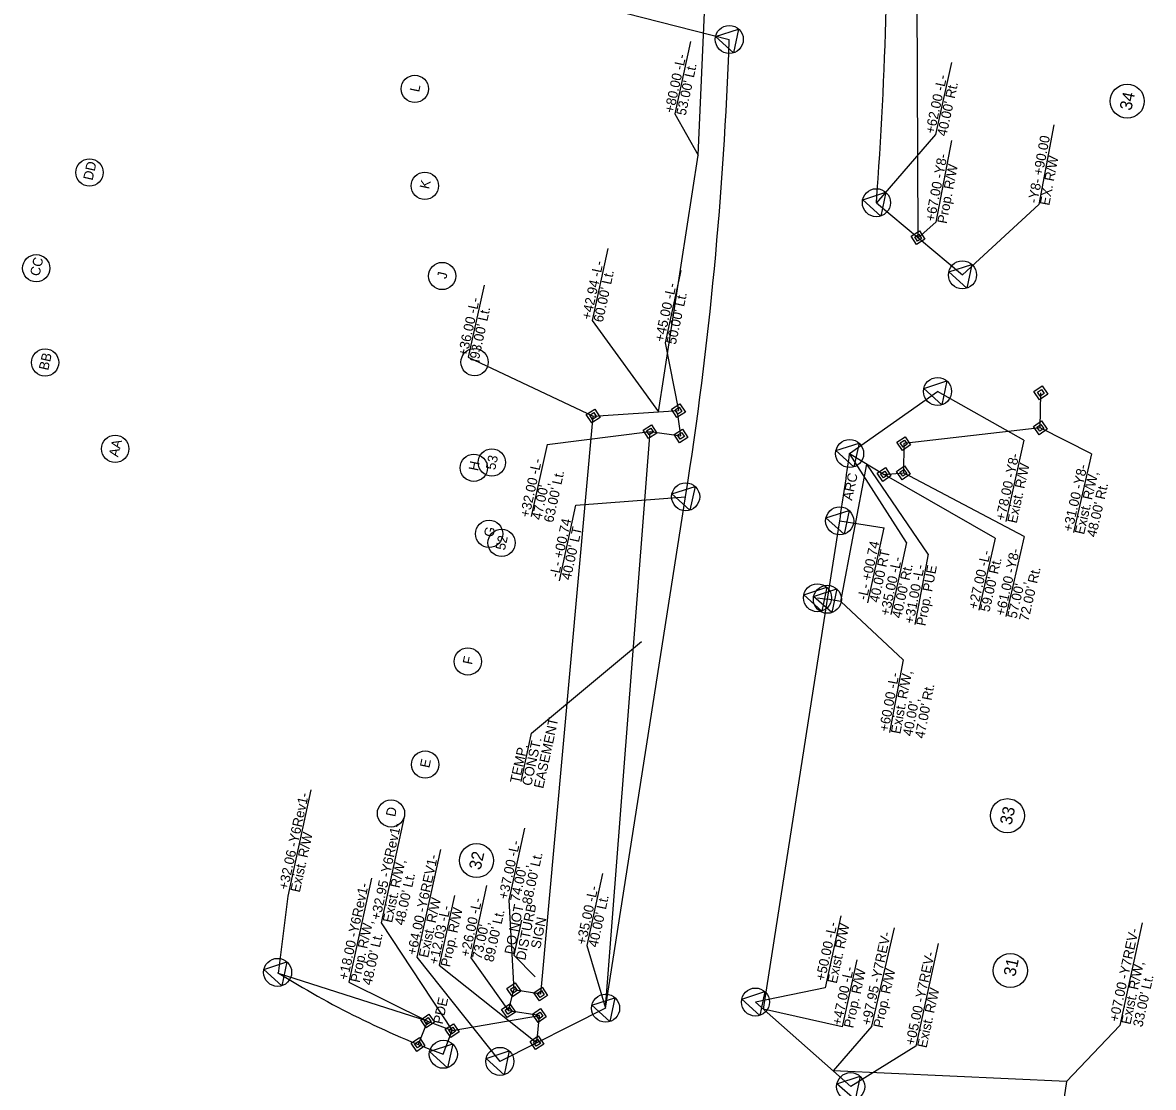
# Model space of a CAD drawing. Extents: x 1610947 to 1617684, y 899814 to 904658.
# Drawn here: x 1616296 to 1616876, y 901678 to 902225 of the extents above; entities that cross this region are included whole.
import ezdxf

# ---------------------------------------------------------------- set-up
doc = ezdxf.new("R2010")
doc.units = 0
for name, color, linetype in [('Default', 7, 'Continuous'), ('Prop Conc 1ft 6in Curb and Gutter', 7, 'Continuous'), ('Prop Dimension', 7, 'Continuous'), ('Prop EOT Dash', 7, 'Continuous'), ('Prop Hatching', 7, 'Continuous'), ('Prop Horizontal Alignment Direction Label', 7, 'Continuous'), ('Prop Horizontal Alignment Station Label', 7, 'Continuous'), ('Prop Horizontal Alignment Tick Label', 7, 'Continuous'), ('Prop ROW Marker CELL', 7, 'Continuous'), ('Prop ROW RW Lines', 7, 'Continuous'), ('Prop ROW Station Offsets', 7, 'Continuous'), ('Scratch_Level_3', 7, 'Continuous'), ('Scratch_Level_8', 7, 'Continuous'), ('Typical Terminator CELL', 7, 'Continuous')]:
    doc.layers.add(name, color=color, linetype=linetype)

msp = doc.modelspace()

# ---------------------------------------------------------------- linework, layer by layer
at = {"layer": 'Default'}
for centre in [(1616330.08, 902148.17), (1616302.78, 902098.97), (1616307.3, 902050.62), (1616343.26, 902006.29)]:
    msp.add_circle(centre, 7, dxfattribs=at)
at = {"layer": 'Prop Conc 1ft 6in Curb and Gutter'}
for p, q in [((1616638.54, 902215.35), (1616630.53, 902178.29)), ((1616596.09, 902109.17), (1616588, 902072.12)), ((1616556.95, 901860.24), (1616613.31, 901907.32)), ((1616551.55, 901835.49), (1616556.95, 901860.24)), ((1616731.63, 901709.85), (1616743.23, 901760.43)), ((1616870.36, 901762.9), (1616858.87, 901710.27)), ((1616723.91, 901743.93), (1616716.4, 901709.5)), ((1616716.4, 901709.5), (1616676.03, 901718.57)), ((1616731.63, 901709.85), (1616711.69, 901686.88)), ((1616858.87, 901710.27), (1616831.42, 901681.38))]:
    msp.add_line(p, q, dxfattribs=at)
for points in [[(1616630.53, 902178.29), (1616642.43, 902157.05)], [(1616588, 902072.12), (1616622.19, 902025.25)]]:
    msp.add_lwpolyline(points, dxfattribs=at)
at = {"layer": 'Prop Dimension'}
for p, q in [((1616551.8, 901764.36), (1616547.86, 901746.3)), ((1616547.86, 901746.3), (1616558.83, 901735.19))]:
    msp.add_line(p, q, dxfattribs=at)
at = {"layer": 'Prop EOT Dash'}
for points in [[(1616751.83, 902115.45), (1616756.11, 902118.2), (1616758.86, 902113.91), (1616754.58, 902111.16)], [(1616753.58, 902115.06), (1616755.73, 902116.44), (1616757.1, 902114.29), (1616754.96, 902112.92)], [(1616814.76, 902035.72), (1616818.97, 902038.58), (1616821.84, 902034.38), (1616817.63, 902031.51)], [(1616816.53, 902035.38), (1616818.64, 902036.82), (1616820.07, 902034.71), (1616817.97, 902033.28)], [(1616585.07, 902023.88), (1616589.36, 902026.63), (1616592.11, 902022.34), (1616587.82, 902019.59)], [(1616628.85, 902026.67), (1616633.14, 902029.42), (1616635.89, 902025.14), (1616631.6, 902022.39)], [(1616630.61, 902026.29), (1616632.75, 902027.66), (1616634.13, 902025.52), (1616631.99, 902024.15)], [(1616586.83, 902023.49), (1616588.98, 902024.87), (1616590.35, 902022.72), (1616588.21, 902021.35)], [(1616814.53, 902017.72), (1616818.74, 902020.59), (1616821.6, 902016.38), (1616817.39, 902013.51)], [(1616614.26, 902015.92), (1616618.54, 902018.67), (1616621.29, 902014.39), (1616617.01, 902011.64)], [(1616616.01, 902015.54), (1616618.16, 902016.91), (1616619.53, 902014.77), (1616617.39, 902013.4)], [(1616630.1, 902013.7), (1616634.39, 902016.45), (1616637.13, 902012.16), (1616632.85, 902009.41)], [(1616631.86, 902013.31), (1616634, 902014.69), (1616635.38, 902012.55), (1616633.23, 902011.17)], [(1616816.3, 902017.38), (1616818.4, 902018.82), (1616819.83, 902016.71), (1616817.73, 902015.28)], [(1616744.42, 902009.64), (1616748.62, 902012.51), (1616751.49, 902008.3), (1616747.28, 902005.43)], [(1616746.18, 902009.31), (1616748.29, 902010.74), (1616749.72, 902008.63), (1616747.62, 902007.2)], [(1616734.33, 901993.75), (1616738.53, 901996.62), (1616741.4, 901992.41), (1616737.19, 901989.55)], [(1616744.22, 901994.64), (1616748.43, 901997.51), (1616751.29, 901993.3), (1616747.08, 901990.43)], [(1616736.09, 901993.42), (1616738.2, 901994.85), (1616739.63, 901992.75), (1616737.53, 901991.31)], [(1616745.99, 901994.31), (1616748.09, 901995.74), (1616749.52, 901993.64), (1616747.42, 901992.2)], [(1616544.31, 901729.18), (1616548.52, 901732.04), (1616551.38, 901727.84), (1616547.18, 901724.97)], [(1616546.08, 901728.84), (1616548.18, 901730.28), (1616549.62, 901728.17), (1616547.51, 901726.74)], [(1616558.14, 901727.01), (1616562.35, 901729.88), (1616565.21, 901725.67), (1616561.01, 901722.81)], [(1616559.91, 901726.68), (1616562.01, 901728.11), (1616563.45, 901726.01), (1616561.34, 901724.57)], [(1616541.62, 901718.47), (1616545.83, 901721.33), (1616548.69, 901717.12), (1616544.49, 901714.26)], [(1616543.39, 901718.13), (1616545.49, 901719.56), (1616546.93, 901717.46), (1616544.82, 901716.03)], [(1616557.43, 901715.99), (1616561.64, 901718.86), (1616564.5, 901714.65), (1616560.29, 901711.78)], [(1616500.09, 901713.19), (1616504.3, 901716.06), (1616507.17, 901711.85), (1616502.96, 901708.98)], [(1616501.86, 901712.86), (1616503.97, 901714.29), (1616505.4, 901712.18), (1616503.29, 901710.75)], [(1616559.2, 901715.66), (1616561.3, 901717.09), (1616562.73, 901714.98), (1616560.63, 901713.55)], [(1616512.68, 901708.28), (1616516.89, 901711.14), (1616519.75, 901706.94), (1616515.55, 901704.07)], [(1616514.45, 901707.94), (1616516.55, 901709.38), (1616517.99, 901707.27), (1616515.88, 901705.84)], [(1616495.19, 901701.15), (1616499.39, 901704.02), (1616502.26, 901699.81), (1616498.05, 901696.95)], [(1616496.95, 901700.82), (1616499.06, 901702.25), (1616500.49, 901700.15), (1616498.39, 901698.71)], [(1616556.21, 901702.04), (1616560.42, 901704.91), (1616563.28, 901700.7), (1616559.07, 901697.83)], [(1616557.97, 901701.7), (1616560.08, 901703.14), (1616561.51, 901701.03), (1616559.41, 901699.6)]]:
    msp.add_lwpolyline(points, close=True, dxfattribs=at)
at = {"layer": 'Prop Hatching'}
for centre, radius in [((1616862.65, 902184.77), 8.75), ((1616536.6, 901999.26), 7), ((1616541.61, 901958.01), 7), ((1616801.16, 901817.93), 8.75), ((1616528.74, 901794.9), 8.75), ((1616802.68, 901738.41), 8.75)]:
    msp.add_circle(centre, radius, dxfattribs=at)
at = {"layer": 'Prop Horizontal Alignment Direction Label'}
for p, q in [((1616755.34, 902114.68), (1616754.55, 902301.94)), ((1616818.06, 902017.05), (1616818.3, 902035.05)), ((1616588.59, 902023.11), (1616632.37, 902025.9)), ((1616561.68, 901726.34), (1616588.59, 902023.11)), ((1616633.62, 902012.93), (1616631.99, 902024.15)), ((1616594.96, 901719.11), (1616617.77, 902015.16)), ((1616617.77, 902015.16), (1616633.62, 902012.93)), ((1616818.06, 902017.05), (1616747.95, 902008.97)), ((1616747.95, 902008.97), (1616747.76, 901993.97)), ((1616720.19, 902003.85), (1616737.86, 901993.08)), ((1616737.86, 901993.08), (1616747.76, 901993.97)), ((1616545.16, 901717.79), (1616547.85, 901728.51)), ((1616561.68, 901726.34), (1616547.85, 901728.51)), ((1616560.97, 901715.32), (1616545.16, 901717.79)), ((1616559.74, 901701.37), (1616560.97, 901715.32))]:
    msp.add_line(p, q, dxfattribs=at)
at = {"layer": 'Prop Horizontal Alignment Station Label'}
for centre in [(1616497.08, 902191.06), (1616502.2, 902141.28), (1616511.08, 902095.01), (1616527.74, 902050.78), (1616527.34, 901996.56), (1616535.16, 901962.63), (1616524.27, 901897.13), (1616502.35, 901844.16), (1616484.84, 901819.12)]:
    msp.add_circle(centre, 7, dxfattribs=at)
at = {"layer": 'Prop Horizontal Alignment Tick Label'}
for p, q in [((1616772.44, 902164.55), (1616764.48, 902122.62)), ((1616633.57, 902097.79), (1616625.48, 902060.75)), ((1616532.6, 902090.32), (1616524.51, 902053.27)), ((1616564.91, 902008.5), (1616617.77, 902015.16)), ((1616564.91, 902008.5), (1616556.82, 901971.46)), ((1616844.31, 902003.69), (1616835.02, 901963.27)), ((1616794.92, 901960.44), (1616737.86, 901993.08)), ((1616794.92, 901960.44), (1616786.43, 901923.48)), ((1616809.81, 901961.34), (1616800.34, 901920.12)), ((1616553.35, 901811.6), (1616545.26, 901774.56)), ((1616533.82, 901782.09), (1616525.73, 901745.04)), ((1616517.41, 901777.02), (1616509.57, 901741.14))]:
    msp.add_line(p, q, dxfattribs=at)
for points in [[(1616764.48, 902122.62), (1616755.34, 902114.68)], [(1616625.48, 902060.75), (1616632.37, 902025.9)], [(1616524.51, 902053.27), (1616588.59, 902023.11)], [(1616844.31, 902003.69), (1616818.06, 902017.05)], [(1616809.81, 901961.34), (1616747.76, 901993.97)], [(1616545.26, 901774.56), (1616547.85, 901728.51)], [(1616525.73, 901745.04), (1616545.16, 901717.79)], [(1616509.57, 901741.14), (1616559.74, 901701.37)]]:
    msp.add_lwpolyline(points, dxfattribs=at)
at = {"layer": 'Prop ROW Marker CELL'}
for p, q in [((1616658.43, 902216.46), (1616658.43, 902216.46)), ((1616733.94, 902132.64), (1616733.94, 902132.64)), ((1616755.34, 902114.68), (1616755.34, 902114.68)), ((1616778.09, 902095.58), (1616778.09, 902095.58)), ((1616765.31, 902035.74), (1616765.31, 902035.74)), ((1616818.3, 902035.05), (1616818.3, 902035.05)), ((1616632.37, 902025.9), (1616632.37, 902025.9)), ((1616588.59, 902023.11), (1616588.59, 902023.11)), ((1616617.77, 902015.16), (1616617.77, 902015.16)), ((1616818.06, 902017.05), (1616818.06, 902017.05)), ((1616633.62, 902012.93), (1616633.62, 902012.93)), ((1616747.95, 902008.97), (1616747.95, 902008.97)), ((1616720.19, 902003.85), (1616720.19, 902003.85)), ((1616737.86, 901993.08), (1616737.86, 901993.08)), ((1616747.76, 901993.97), (1616747.76, 901993.97)), ((1616636.05, 901981.65), (1616636.05, 901981.65)), ((1616715.09, 901969.28), (1616715.09, 901969.28)), ((1616703.7, 901929.83), (1616703.7, 901929.83)), ((1616708.79, 901929.03), (1616708.79, 901929.03)), ((1616426.64, 901737.49), (1616426.64, 901737.49)), ((1616547.85, 901728.51), (1616547.85, 901728.51)), ((1616561.68, 901726.34), (1616561.68, 901726.34)), ((1616594.96, 901719.11), (1616594.96, 901719.11)), ((1616671.88, 901722.25), (1616671.88, 901722.25)), ((1616503.63, 901712.52), (1616503.63, 901712.52)), ((1616545.16, 901717.79), (1616545.16, 901717.79)), ((1616560.97, 901715.32), (1616560.97, 901715.32)), ((1616516.22, 901707.61), (1616516.22, 901707.61)), ((1616559.74, 901701.37), (1616559.74, 901701.37)), ((1616498.72, 901700.48), (1616498.72, 901700.48)), ((1616511.68, 901695.43), (1616511.68, 901695.43)), ((1616540.73, 901691.79), (1616540.73, 901691.79)), ((1616720.73, 901678.85), (1616720.73, 901678.85))]:
    msp.add_line(p, q, dxfattribs=at)
for points in [[(1616660.65, 902209.6), (1616651.39, 902217.95), (1616663.25, 902221.82)], [(1616736.17, 902125.78), (1616726.9, 902134.14), (1616738.76, 902138.01)], [(1616780.32, 902088.72), (1616771.05, 902097.08), (1616782.91, 902100.95)], [(1616767.53, 902028.88), (1616758.26, 902037.24), (1616770.13, 902041.11)], [(1616722.42, 901996.99), (1616713.15, 902005.35), (1616725.01, 902009.22)], [(1616638.27, 901974.79), (1616629.01, 901983.15), (1616640.87, 901987.02)], [(1616717.31, 901962.42), (1616708.04, 901970.78), (1616719.91, 901974.65)], [(1616705.92, 901922.97), (1616696.65, 901931.33), (1616708.52, 901935.2)], [(1616711.01, 901922.17), (1616701.74, 901930.53), (1616713.61, 901934.4)], [(1616428.87, 901730.62), (1616419.6, 901738.98), (1616431.46, 901742.85)], [(1616597.18, 901712.24), (1616587.92, 901720.6), (1616599.78, 901724.47)], [(1616674.1, 901715.39), (1616664.83, 901723.75), (1616676.7, 901727.62)], [(1616513.9, 901688.56), (1616504.63, 901696.92), (1616516.5, 901700.79)], [(1616542.95, 901684.93), (1616533.69, 901693.29), (1616545.55, 901697.16)], [(1616722.96, 901671.99), (1616713.69, 901680.34), (1616725.55, 901684.21)]]:
    msp.add_lwpolyline(points, close=True, dxfattribs=at)
for centre in [(1616658.43, 902216.46), (1616733.94, 902132.64), (1616778.09, 902095.58), (1616765.31, 902035.74), (1616720.19, 902003.85), (1616636.05, 901981.65), (1616715.09, 901969.28), (1616703.7, 901929.83), (1616708.79, 901929.03), (1616426.64, 901737.49), (1616594.96, 901719.11), (1616671.88, 901722.25), (1616511.68, 901695.43), (1616540.73, 901691.79), (1616720.73, 901678.85)]:
    msp.add_circle(centre, 7.2, dxfattribs=at)
at = {"layer": 'Prop ROW RW Lines'}
for p, q in [((1616733.94, 902132.64), (1616778.09, 902095.58)), ((1616720.19, 902003.85), (1616765.31, 902035.74)), ((1616594.96, 901719.11), (1616636.05, 901981.65)), ((1616708.79, 901929.03), (1616715.09, 901969.28)), ((1616703.7, 901929.83), (1616708.79, 901929.03)), ((1616594.96, 901719.11), (1616540.73, 901691.79)), ((1616720.73, 901678.85), (1616671.88, 901722.25))]:
    msp.add_line(p, q, dxfattribs=at)
for centre, radius, start, end in [((1614681.37, 902285.15), 2058.23, 355.7505, 1.30006), ((1614699.62, 902284.7), 1960, 351.10533, 358.00462), ((1614700.19, 902284.62), 2039.43, 351.10516, 352.08705), ((1616674.24, 902131.08), 465, 237.82721, 249.53684)]:
    msp.add_arc(centre, radius, start, end, dxfattribs=at)
at = {"layer": 'Prop ROW Station Offsets'}
for p, q in [((1616587.27, 902234.54), (1616658.43, 902216.46)), ((1616772.43, 902204.66), (1616764.34, 902167.61)), ((1616825.07, 902172.68), (1616817.29, 902131.72)), ((1616778.09, 902095.58), (1616817.29, 902131.72)), ((1616809.54, 902010.65), (1616800.44, 901968.95)), ((1616749.44, 901958.19), (1616720.19, 902003.85)), ((1616579.72, 901977.29), (1616636.05, 901981.65)), ((1616571.27, 901938.59), (1616579.72, 901977.29)), ((1616715.09, 901969.28), (1616737.96, 901965.73)), ((1616729.56, 901927.26), (1616737.96, 901965.73)), ((1616749.44, 901958.19), (1616741.35, 901921.15)), ((1616431.99, 901776.56), (1616443.92, 901831.23)), ((1616510.24, 901800.55), (1616498.16, 901745.23)), ((1616593.43, 901788.31), (1616585.34, 901751.26)), ((1616427.02, 901736.91), (1616431.99, 901776.56)), ((1616715.69, 901766.57), (1616707.6, 901729.52)), ((1616765.64, 901752.23), (1616754.15, 901699.59)), ((1616498.16, 901745.23), (1616540.73, 901691.79)), ((1616707.6, 901729.52), (1616671.88, 901722.25))]:
    msp.add_line(p, q, dxfattribs=at)
for points in [[(1616764.34, 902167.61), (1616733.94, 902132.64)], [(1616809.54, 902010.65), (1616765.31, 902035.74)], [(1616585.34, 901751.26), (1616594.96, 901719.11)], [(1616754.15, 901699.59), (1616720.73, 901678.85)]]:
    msp.add_lwpolyline(points, dxfattribs=at)
at = {"layer": 'Scratch_Level_3'}
for p, q in [((1616642.43, 902157.05), (1616649.42, 902312.76)), ((1616622.19, 902025.25), (1616642.43, 902157.05)), ((1616715.7, 901927.95), (1616728.99, 901998.49)), ((1616760.46, 901952.18), (1616728.99, 901998.49)), ((1616760.46, 901952.18), (1616753.61, 901916.1)), ((1616676.03, 901718.57), (1616708.79, 901929.03)), ((1616715.7, 901927.95), (1616708.79, 901929.03)), ((1616747.72, 901897.93), (1616740.65, 901860.68)), ((1616503.63, 901712.52), (1616427.02, 901736.91)), ((1616516.22, 901707.61), (1616560.97, 901715.32)), ((1616831.42, 901681.38), (1616711.69, 901686.88)), ((1616831.42, 901681.38), (1616830.23, 901673.44))]:
    msp.add_line(p, q, dxfattribs=at)
msp.add_lwpolyline([(1616747.72, 901897.93), (1616715.7, 901927.95)], dxfattribs=at)
at = {"layer": 'Scratch_Level_8'}
for p, q in [((1616491.62, 901817.42), (1616479.71, 901762.88)), ((1616474.77, 901785.78), (1616463.12, 901732.41)), ((1616479.71, 901762.88), (1616516.22, 901707.61)), ((1616463.12, 901732.41), (1616503.63, 901712.52))]:
    msp.add_line(p, q, dxfattribs=at)
at = {"layer": 'Typical Terminator CELL'}
for p, q in [((1616503.63, 901712.52), (1616498.72, 901700.48)), ((1616503.63, 901712.52), (1616516.22, 901707.61)), ((1616511.68, 901695.43), (1616516.22, 901707.61))]:
    msp.add_line(p, q, dxfattribs=at)

# ---------------------------------------------------------------- texts
at = {"layer": 'Default'}
for s, p in [('DD', (1616331.65, 902143.81)), ('CC', (1616304.35, 902094.61)), ('BB', (1616308.88, 902046.27)), ('AA', (1616344.8, 902001.78))]:
    msp.add_text(s, height=5, rotation=77.19821, dxfattribs=at).set_placement(p)
at = {"layer": 'Prop Conc 1ft 6in Curb and Gutter'}
for s, rotation, p in [('+80.00 -L-', 77.79921, (1616629.92, 902178.42)), ("53.00' Lt.", 77.79921, (1616636.03, 902177.1)), ('+42.94 -L-', 77.68623, (1616587.39, 902072.26)), ("60.00' Lt.", 77.68623, (1616593.5, 902070.93)), ('EASEMENT', 77.68623, (1616562.92, 901831.6)), ('TEMP.', 77.68623, (1616550.71, 901834.27)), ('CONST.', 77.68623, (1616556.81, 901832.93)), ('+07.00 -Y7REV-', 77.68623, (1616858.18, 901711.77)), ('+97.95 -Y7REV-', 77.68623, (1616731.02, 901709.98)), ('Exist. R/W,', 77.68623, (1616864.28, 901710.43)), ('+47.00 -L-', 77.68623, (1616715.88, 901709.92)), ('Prop. R/W', 77.68623, (1616721.98, 901708.58)), ('Prop. R/W', 77.68623, (1616737.12, 901708.65)), ("33.00' Lt.", 77.68623, (1616870.39, 901709.1))]:
    msp.add_text(s, height=5, rotation=rotation, dxfattribs=at).set_placement(p)
at = {"layer": 'Prop Dimension'}
for s, p in [('DO NOT', (1616547.87, 901746.35)), ('DISTURB', (1616553.74, 901743.4)), ('SIGN', (1616561.39, 901749.32))]:
    msp.add_text(s, height=5, rotation=78.70542, dxfattribs=at).set_placement(p)
at = {"layer": 'Prop Hatching'}
for s, height, rotation, p in [('34', 6.25, 77.71667, (1616864.73, 902179.64)), ('53', 5, 78.09451, (1616538.29, 901995.16)), ('52', 5, 78.09451, (1616543.3, 901953.91)), ('33', 6.25, 77.71667, (1616803.24, 901812.79)), ('32', 6.25, 77.71667, (1616530.82, 901789.77)), ('31', 6.25, 77.71667, (1616805.13, 901735))]:
    msp.add_text(s, height=height, rotation=rotation, dxfattribs=at).set_placement(p)
at = {"layer": 'Prop Horizontal Alignment Station Label'}
for s, p in [('L', (1616499.24, 902189.16)), ('K', (1616504.36, 902139.37)), ('J', (1616513.27, 902093.3)), ('I', (1616530.19, 902050.27)), ('H', (1616529.49, 901994.66)), ('G', (1616537.29, 901960.62)), ('F', (1616526.43, 901895.22)), ('E', (1616504.48, 901842.16)), ('D', (1616486.97, 901817.1))]:
    msp.add_text(s, height=5, rotation=78.09451, dxfattribs=at).set_placement(p)
at = {"layer": 'Prop Horizontal Alignment Tick Label'}
for s, rotation, p in [('+67.00 -Y8-', 79.24937, (1616763.87, 902122.74)), ('Prop. R/W', 79.24937, (1616770.01, 902121.58)), ('+45.00 -L-', 77.68623, (1616624.87, 902060.88)), ("50.00' Lt.", 77.68623, (1616630.97, 902059.55)), ('+36.00 -L-', 77.68623, (1616523.9, 902053.4)), ("93.00' Lt.", 77.68623, (1616530.01, 902052.07)), ('+32.00 -L-', 77.68623, (1616555.79, 901970.77)), ('+31.00 -Y8-', 77.05555, (1616834.41, 901963.41)), ("63.00' Lt.", 77.68623, (1616568, 901968.11)), ('Exist. R/W,', 77.05555, (1616840.5, 901962.01)), ("47.00',", 77.68623, (1616561.9, 901969.44)), ("48.00' Rt.", 77.05555, (1616846.59, 901960.61)), ('+27.00 -L-', 77.05555, (1616785.82, 901923.63)), ('+61.00 -Y8-', 77.05555, (1616799.73, 901920.26)), ("59.00' Rt.", 77.05555, (1616791.91, 901922.23)), ("72.00' Rt.", 77.05555, (1616811.91, 901917.46)), ("57.00',", 77.05555, (1616805.82, 901918.86)), ('+37.00 -L-', 77.68623, (1616544.65, 901774.69)), ("88.00' Lt.", 77.68623, (1616556.86, 901772.02)), ("74.00',", 77.68623, (1616550.76, 901773.36)), ('+12.03 -L-', 77.68623, (1616508.96, 901741.28)), ('Prop. R/W', 77.68623, (1616515.07, 901739.94)), ('+26.00 -L-', 77.68623, (1616525.12, 901745.18)), ("89.00' Lt.", 77.68623, (1616537.34, 901742.51)), ("73.00',", 77.68623, (1616531.23, 901743.84))]:
    msp.add_text(s, height=5, rotation=rotation, dxfattribs=at).set_placement(p)
at = {"layer": 'Prop ROW Station Offsets'}
for s, rotation, p in [('+62.00 -L-', 77.68623, (1616763.73, 902167.75)), ("40.00' Rt.", 77.68623, (1616769.84, 902166.41)), ('-Y8- +90.00', 79.24937, (1616816.5, 902132.09)), ('EX. R/W', 79.24937, (1616822.64, 902130.93)), ('+78.00 -Y8-', 77.68623, (1616799.83, 901969.09)), ('Exist. R/W', 77.68623, (1616805.93, 901967.76)), ('ARC', 77.68623, (1616721.42, 901979.49)), ('-L- +00.74', 77.68623, (1616570.89, 901939.93)), ("40.00' LT", 77.68623, (1616576.99, 901938.6)), ('-L- +00.74', 77.68623, (1616729, 901928.37)), ('40.00 RT', 77.68623, (1616735.1, 901927.03)), ('+35.00 -L-', 77.68623, (1616740.55, 901920.29)), ("40.00' Rt.", 77.68623, (1616746.65, 901918.96)), ('+32.06 -Y6Rev1-', 77.68623, (1616431.89, 901779.6)), ('Exist. R/W', 77.68623, (1616438, 901778.26)), ('+64.00 -Y6REV1-', 77.68623, (1616497.75, 901746.04)), ('Exist. R/W', 77.68623, (1616503.85, 901744.71)), ('+35.00 -L-', 77.68623, (1616584.73, 901751.39)), ("40.00' Lt.", 77.68623, (1616590.84, 901750.06)), ('+50.00 -L-', 77.68623, (1616707.44, 901732.81)), ('Exist. R/W', 77.68623, (1616713.55, 901731.48)), ('+05.00 -Y7REV-', 77.68623, (1616753.54, 901699.73)), ('Exist. R/W', 77.68623, (1616759.65, 901698.39))]:
    msp.add_text(s, height=5, rotation=rotation, dxfattribs=at).set_placement(p)
at = {"layer": 'Scratch_Level_3'}
for s, p in [('+31.00 -L-', (1616753, 901916.22)), ('Prop. PUE', (1616759.14, 901915.06)), ('+60.00 -L-', (1616740.04, 901860.79)), ('Exist. R/W,', (1616746.18, 901859.63)), ("47.00' Rt.", (1616758.46, 901857.3)), ("40.00',", (1616752.32, 901858.46))]:
    msp.add_text(s, height=5, rotation=79.24937, dxfattribs=at).set_placement(p)
at = {"layer": 'Scratch_Level_8'}
for s, p in [('+32.95 -Y6Rev1-', (1616479.23, 901764.04)), ('Exist. R/W,', (1616485.34, 901762.71)), ('+18.00 -Y6Rev1-', (1616462.63, 901733.26)), ("48.00' Lt.", (1616491.44, 901761.37)), ('Prop. R/W,', (1616468.74, 901731.93)), ("48.00' Lt.", (1616474.84, 901730.6)), ('PDE', (1616511.26, 901710.59))]:
    msp.add_text(s, height=5, rotation=77.68623, dxfattribs=at).set_placement(p)

doc.saveas('drawing.dxf')
